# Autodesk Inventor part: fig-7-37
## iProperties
Shininess: 77.0
Length Units: 11269
Angle Units: 11279
Time Units: 11290
Mass Units: 11283
Length Display Precision: 3
Angle Display Precision: 2
Created: 2002-01
Part Number: fig-7-37
Document SubType Name: Modeling
Designer: ***
Density: 0.0
Volumn: 0.0
Area: 0.0
PropertySet Name: Model Information
Control State: 0
Master: False
Checked Out: False
Author: ***
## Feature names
1. Extrusion1
2. Fillet1
3. Extrusion2
4. Extrusion3
5. Chamfer1
